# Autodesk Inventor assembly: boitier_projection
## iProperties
Created: 2011-01
Part Number: boitier_projection
Document SubType Name: Assembly
Designer: eric
Mass: 591.763 g
Surface Area: 6428.9 cm^2
Volume: 591.763 cm^3
Density: 1 g/cm^3
Norme de conversion: IGES 5.3
Nom du fichier: No Iges File Name specified
Préprocesseur: Autodesk Inventor 2011
Postprocesseur: Build: 342, Release: 2008 SP3 - Date: Tue 05/27/2008
Unités envoyées: MM
Incertitude: 0.01
Author: eric
